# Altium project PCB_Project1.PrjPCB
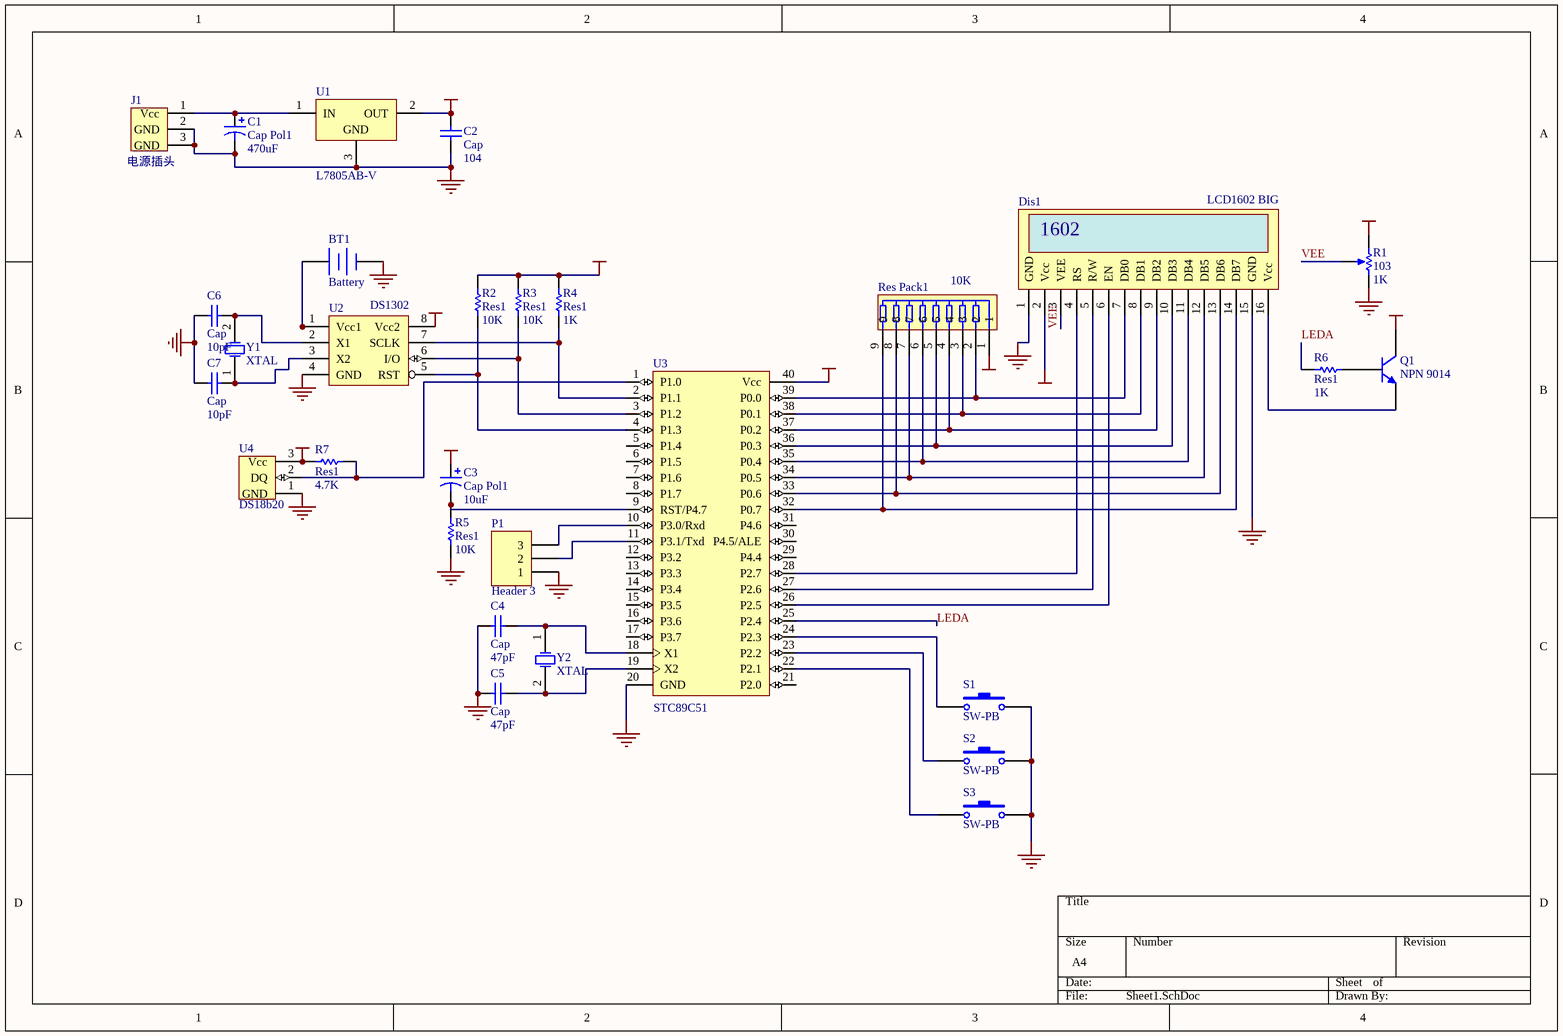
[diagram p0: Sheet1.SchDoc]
1 sheet, 29 parts. Net scope: global (net labels, ports and power ports of the same name join across sheets).
Board file: PCB1.PcbDoc

## Sheet Sheet1.SchDoc
size A4

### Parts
BT1  Battery  [BAT-2]
C1  Cap Pol1  value 470uF  [CAPPR2-5x6.8]
C2  Cap  value 104  [CAPR5.08-7.8x3.2]
C3  Cap Pol1  value 10uF  [RB7.6-15]
C4  Cap  value 47pF  [CAPR5.08-7.8x3.2]
C5  Cap  value 47pF  [CAPR5.08-7.8x3.2]
C6  Cap  value 10pF  [RAD-0.3]
C7  Cap  value 10pF  [RAD-0.3]
Dis1  LCD1602 BIG  [1602]
J1  电源插头  [电源接头小]
P1  Header 3  [HDR1X3]
Q1  NPN 9014  [BCY-W3]
R1  103  value 1K  [VR5]
R2  Res1  value 10K  [AXIAL-0.3]
R3  Res1  value 10K  [AXIAL-0.3]
R4  Res1  value 1K  [AXIAL-0.3]
R5  Res1  value 10K  [AXIAL-0.3]
R6  Res1  value 1K  [AXIAL-0.3]
R7  Res1  value 4.7K  [AXIAL-0.3]
Res_Pack1  10K  [Res Pack]
S1  SW-PB  [SPST-2]
S2  SW-PB  [SPST-2]
S3  SW-PB  [SPST-2]
U1  L7805AB-V  [TO220ABN]
U2  DS1302  [DIP8]
U3  STC89C51  [DIP40]
U4  DS18b20  [18b20]
Y1  XTAL  [BCY-W2/D3.1]
Y2  XTAL  [BCY-W2/D3.1]

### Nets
GND: BT1.2(-) C1.2 C2.1 C4.1 C5.1 C6.1 C7.1 Dis1.1(GND) Dis1.15(GND) J1.2(GND) J1.3(GND) P1.1 R1.2(BOT) R5.1 S1.2 S2.2 S3.2 U1.3(GND) U2.4(GND) U3.20(GND) U4.1(GND)
VCC: C2.2 C3.1 Dis1.2(Vcc) Q1.1(C) R1.1(TOP) R2.2 R3.2 R4.2 R7.1 Res_Pack1.1 U1.2(OUT) U2.8(Vcc2) U3.40(Vcc) U4.3(Vcc)
LEDA: R6.1 U3.25(P2.4)
VEE: Dis1.3(VEE) R1.3(TAP)
NetBT1_1: BT1.1(+) U2.1(Vcc1)
NetC1_1: C1.1 J1.1(Vcc) U1.1(IN)
NetC3_2: C3.2 R5.2 U3.9(RST/P4.7)
NetC4_2: C4.2 U3.18(X1) Y2.1(OSC1)
NetC5_2: C5.2 U3.19(X2) Y2.2(OSC2)
NetC6_2: C6.2 U2.2(X1) Y1.2(OSC2)
NetC7_2: C7.2 U2.3(X2) Y1.1(OSC1)
NetDis1_4: Dis1.4(RS) U3.28(P2.7)
NetDis1_5: Dis1.5(R/W) U3.27(P2.6)
NetDis1_6: Dis1.6(EN) U3.26(P2.5)
NetDis1_7: Dis1.7(DB0) Res_Pack1.2 U3.39(P0.0)
NetDis1_8: Dis1.8(DB1) Res_Pack1.3 U3.38(P0.1)
NetDis1_9: Dis1.9(DB2) Res_Pack1.4 U3.37(P0.2)
NetDis1_10: Dis1.10(DB3) Res_Pack1.5 U3.36(P0.3)
NetDis1_11: Dis1.11(DB4) Res_Pack1.6 U3.35(P0.4)
NetDis1_12: Dis1.12(DB5) Res_Pack1.7 U3.34(P0.5)
NetDis1_13: Dis1.13(DB6) Res_Pack1.8 U3.33(P0.6)
NetDis1_14: Dis1.14(DB7) Res_Pack1.9 U3.32(P0.7)
NetDis1_16: Dis1.16(Vcc) Q1.3(E)
NetP1_2: P1.2 U3.11(P3.1/Txd)
NetP1_3: P1.3 U3.10(P3.0/Rxd)
NetQ1_2: Q1.2(B) R6.2
NetR2_1: R2.1 U2.5(RST) U3.4(P1.3)
NetR3_1: R3.1 U2.6(I/O) U3.3(P1.2)
NetR4_1: R4.1 U2.7(SCLK) U3.2(P1.1)
NetR7_2: R7.2 U3.1(P1.0) U4.2(DQ)
NetS1_1: S1.1 U3.24(P2.3)
NetS2_1: S2.1 U3.23(P2.2)
NetS3_1: S3.1 U3.22(P2.1)

Not connected (* = marked no-connect by the designer): U3 5(P1.4) 6(P1.5) 7(P1.6) 8(P1.7) 12(P3.2) 13(P3.3) 14(P3.4) 15(P3.5) 16(P3.6) 17(P3.7) 21(P2.0) 29(P4.4) 30(P4.5/ALE) 31(P4.6)

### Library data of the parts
BT1 = Battery: Multicell Battery
C1 C3 = Cap Pol1: Polarized Capacitor (Radial)
C2 C4-C7 = Cap: Capacitor
P1 = Header 3: Header, 3-Pin
Q1 = NPN: NPN Bipolar Transistor
R1 = RPot: Potentiometer; Sim Note: Enter the Resistance value and the set point into parameter fields.; Set Position: 0.5
R2-R7 = Res1: Resistor
Res_Pack1 = RES Pack
S1-S3 = SW-PB: Switch
U1 = L7805AB-V: Precision 1A Regulator; Note: Tab is connected to pin 3 (GND).
Y1 Y2 = XTAL: Crystal Oscillator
